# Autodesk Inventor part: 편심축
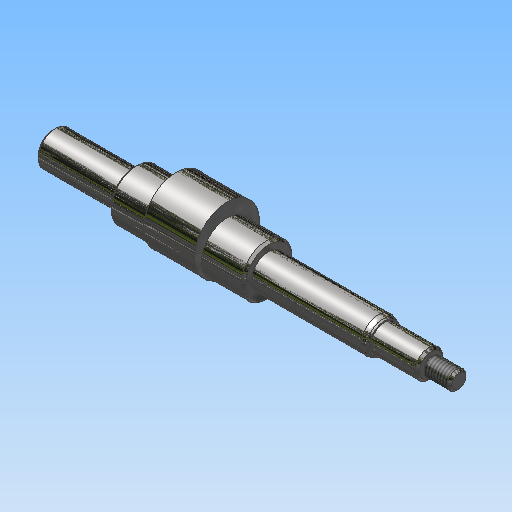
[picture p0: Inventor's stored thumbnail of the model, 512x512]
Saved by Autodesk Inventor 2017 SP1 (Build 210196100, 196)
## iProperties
Created: 2015-09
Part Number: 편심축
Material: 강철, 연강
Document SubType Name: Modeling
Designer: mduedu
Density: 1 g/cm^3
Appearance: 반광택
Author: mduedu
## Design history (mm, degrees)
sketch "스케치1"
  geometry: L1 (-87.5, 0)-(87.5, 0); L2 (-87.5, 0)-(-87.5, 7.5); L3 (-87.5, 7.5)-(-52.5, 7.5); L4 (-52.5, 7.5)-(-52.5, 11); L5 (-52.5, 11)-(5.5, 11); L6 (5.5, 11)-(5.5, 7.5); L7 (5.5, 7.5)-(53.855, 7.5); L8 (55.5, 6.55)-(55.5, 6); L9 (55.5, 6)-(75.5, 6); L10 (75.5, 6)-(75.5, 3); L11 (75.5, 3)-(76.5, 3); L12 (76.5, 3)-(76.5, 4); L13 (76.5, 4)-(87.5, 4); L14 (87.5, 4)-(87.5, 0); L15 (55.5, 6.55)-(53.855, 7.5); 2 further points
  constraints: 30 end point, 10 parallel, 2 perpendicular, 1 coincident, 1 collinear, 1 horizontal, 1 midpoint
  dimensions: "d0" = 35 distance of L2.end L3.end; "d2" = 58 distance of L4.end L5.end; "d4" = 175 distance of L1.start L1.end; "d5" = 20 distance of L8.end L9.end; "d6" = 1 distance of L10.end L11.end; "d7" = 8 diameter of L13 L1; "d8" = 6 diameter of L11 L1; "d9" = 12 diameter of L9 L1; "d10" = 15 diameter of L7 L1; "d11" = 22 diameter of L5 L1; "d12" = 15 diameter of L3 L1; "d40" = 13.1 diameter of L8.start L1; "d41" = 30 deg angle of L7 L15; "d43" = 50 distance between parallel lines of L8 L6
revolve "회전1" sketch "스케치1" stored, may be unused: angle "d13" = 90 deg
node "작업 평면1"
sketch "스케치3"
  geometry: C1 r 11 at (0, 0) reference; C2 r 14 at (0, 3); 1 further point
  constraints: 1 centre point, 1 tangent, 1 vertical alignment
  dimensions: "d19" = 28 diameter of C2
extrude "돌출1" join sketch "스케치3" stored distance "d21" = 22; taper "d22" = 0 deg
node "작업 평면2"
sketch "스케치4"
  geometry: L1 (10, 6.55)-(10, -6.55) reference; L2 (-10, 6)-(-10, -6) reference; L3 (10, 0)-(-10, 0); L4 (-5, -2)-(3, -2); L5 (3, 2)-(-5, 2); A1 r 2 centre (3, 0) between (3, -2) and (3, 2); A2 r 2 centre (-5, 0) between (-5, 2) and (-5, -2); 1 further point
  constraints: 6 end point, 4 point on circle, 4 tangent, 2 centre point, 2 midpoint, 2 parallel, 1 point on line
  dimensions: "d23" = 4 distance between parallel lines of L5 L4; "d25" = 12 dimension on A2 A1; "d26" = 3 distance edge to line of A2 L2
extrude "돌출2" cut sketch "스케치4" distance "d27" = 2.5; taper "d28" = 0 deg
chamfer "모따기1" distance "d29" = 1; stored, may be unused: second distance "d30" = 2, angle "d31" = 45 deg
feature "스레드1" dims "d32" = 10, "d33" = 0
chamfer "모따기2" distance "d34" = 1; stored, may be unused: second distance "d35" = 2, angle "d36" = 45 deg
chamfer "모따기3" distance "d37" = 1; stored, may be unused: second distance "d38" = 2, angle "d39" = 45 deg
fillet "모깎기1" dims "d42" = 4
node "솔리드1"
